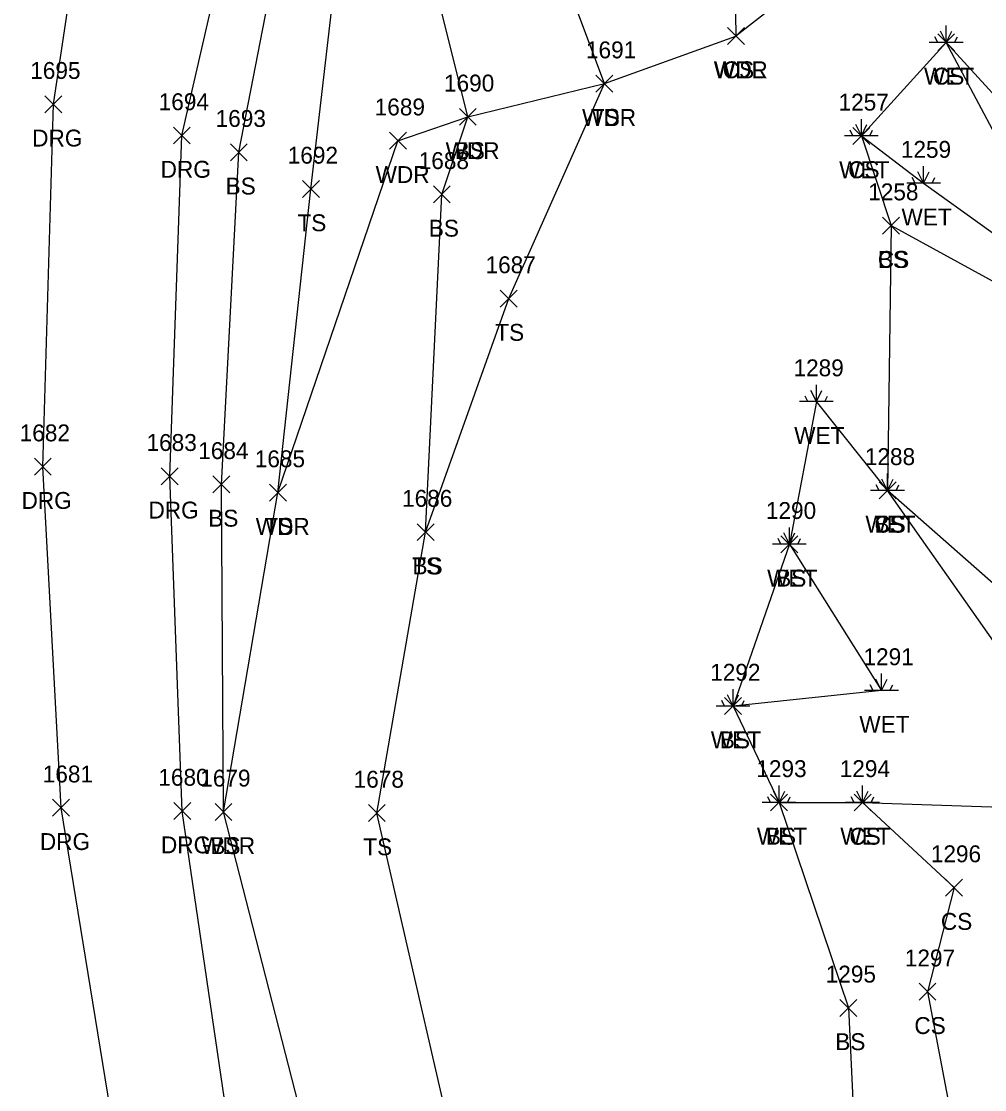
# Model space of a CAD drawing. Extents: x 1551995 to 1555700, y 777276 to 783130.
# Drawn here: x 1554729.1 to 1554843.1, y 777956 to 778082.5 of the extents above; entities that cross this region are included whole.
import ezdxf

# ---------------------------------------------------------------- set-up
doc = ezdxf.new("R2010")
doc.units = 0
for name, color, linetype in [('L_A', 7, 'Continuous'), ('L_I', 7, 'Continuous'), ('L_TIC', 7, 'Continuous'), ('LAWA', 7, 'Continuous'), ('LELB', 7, 'Continuous'), ('LWET', 7, 'Continuous'), ('R_A', 7, 'Continuous'), ('R_I', 7, 'Continuous'), ('R_TIC', 7, 'Continuous'), ('RDG', 7, 'Continuous')]:
    doc.layers.add(name, color=color, linetype=linetype)

msp = doc.modelspace()

# ---------------------------------------------------------------- linework, layer by layer
at = {"layer": 'L_TIC'}
for points in [[(1554812.64, 778079.72), (1554814.64, 778081.72)], [(1554814.64, 778079.72), (1554812.64, 778081.72)], [(1554812.64, 778079.72), (1554814.64, 778081.72)], [(1554814.64, 778079.72), (1554812.64, 778081.72)], [(1554812.64, 778079.72), (1554814.64, 778081.72)], [(1554814.64, 778079.72), (1554812.64, 778081.72)], [(1554837.51, 778078.97), (1554839.51, 778080.97)], [(1554839.51, 778078.97), (1554837.51, 778080.97)], [(1554797.07, 778074.08), (1554799.07, 778076.08)], [(1554799.07, 778074.08), (1554797.07, 778076.08)], [(1554797.07, 778074.08), (1554799.07, 778076.08)], [(1554799.07, 778074.08), (1554797.07, 778076.08)], [(1554780.91, 778070.15), (1554782.91, 778072.15)], [(1554782.91, 778070.15), (1554780.91, 778072.15)], [(1554780.91, 778070.15), (1554782.91, 778072.15)], [(1554782.91, 778070.15), (1554780.91, 778072.15)], [(1554772.64, 778067.32), (1554774.64, 778069.32)], [(1554774.64, 778067.32), (1554772.64, 778069.32)], [(1554827.48, 778067.89), (1554829.48, 778069.89)], [(1554829.48, 778067.89), (1554827.48, 778069.89)], [(1554753.81, 778065.96), (1554755.81, 778067.96)], [(1554755.81, 778065.96), (1554753.81, 778067.96)], [(1554762.34, 778061.61), (1554764.34, 778063.61)], [(1554764.34, 778061.61), (1554762.34, 778063.61)], [(1554777.84, 778060.97), (1554779.84, 778062.97)], [(1554779.84, 778060.97), (1554777.84, 778062.97)], [(1554830.99, 778057.27), (1554832.99, 778059.27)], [(1554832.99, 778057.27), (1554830.99, 778059.27)], [(1554830.99, 778057.27), (1554832.99, 778059.27)], [(1554832.99, 778057.27), (1554830.99, 778059.27)], [(1554785.75, 778048.64), (1554787.75, 778050.64)], [(1554787.75, 778048.64), (1554785.75, 778050.64)], [(1554751.75, 778026.64), (1554753.75, 778028.64)], [(1554753.75, 778026.64), (1554751.75, 778028.64)], [(1554758.44, 778025.67), (1554760.44, 778027.67)], [(1554760.44, 778025.67), (1554758.44, 778027.67)], [(1554758.44, 778025.67), (1554760.44, 778027.67)], [(1554760.44, 778025.67), (1554758.44, 778027.67)], [(1554830.58, 778025.93), (1554832.58, 778027.93)], [(1554832.58, 778025.93), (1554830.58, 778027.93)], [(1554830.58, 778025.93), (1554832.58, 778027.93)], [(1554832.58, 778025.93), (1554830.58, 778027.93)], [(1554775.92, 778020.99), (1554777.92, 778022.99)], [(1554777.92, 778020.99), (1554775.92, 778022.99)], [(1554775.92, 778020.99), (1554777.92, 778022.99)], [(1554777.92, 778020.99), (1554775.92, 778022.99)], [(1554818.96, 778019.55), (1554820.96, 778021.55)], [(1554820.96, 778019.55), (1554818.96, 778021.55)], [(1554812.29, 778000.4), (1554814.29, 778002.4)], [(1554814.29, 778000.4), (1554812.29, 778002.4)], [(1554817.74, 777988.99), (1554819.74, 777990.99)], [(1554819.74, 777988.99), (1554817.74, 777990.99)], [(1554827.62, 777988.99), (1554829.62, 777990.99)], [(1554829.62, 777988.99), (1554827.62, 777990.99)], [(1554752, 777987.87), (1554754, 777989.87)], [(1554754, 777987.87), (1554752, 777989.87)], [(1554752, 777987.87), (1554754, 777989.87)], [(1554754, 777987.87), (1554752, 777989.87)], [(1554770.14, 777987.74), (1554772.14, 777989.74)], [(1554772.14, 777987.74), (1554770.14, 777989.74)], [(1554838.45, 777978.91), (1554840.45, 777980.91)], [(1554840.45, 777978.91), (1554838.45, 777980.91)], [(1554835.31, 777966.58), (1554837.31, 777968.58)], [(1554837.31, 777966.58), (1554835.31, 777968.58)], [(1554825.95, 777964.67), (1554827.95, 777966.67)], [(1554827.95, 777964.67), (1554825.95, 777966.67)]]:
    msp.add_lwpolyline(points, dxfattribs=at)
at = {"layer": 'LAWA'}
for points in [[(1554935.43, 778396.62), (1554932.57, 778365.34), (1554927.8, 778334.86), (1554903.79, 778283.5), (1554902.47, 778219.43), (1554891.48, 778177.56), (1554886.36, 778149.25), (1554864.38, 778127.13), (1554855.54, 778103.27), (1554855.62, 778088.16), (1554832.42, 778095.39), (1554813.64, 778080.72)], [(1554753.38, 777699.82), (1554782.17, 777718.85), (1554781.09, 777755.32), (1554779.76, 777796.52), (1554779.3, 777834.65), (1554766.43, 777889.19), (1554764.95, 777942.26), (1554753, 777988.87), (1554759.44, 778026.67), (1554773.64, 778068.32), (1554781.91, 778071.15), (1554798.07, 778075.08), (1554813.64, 778080.72)]]:
    msp.add_lwpolyline(points, dxfattribs=at)
at = {"layer": 'LELB'}
for points in [[(1554968.28, 778312.04), (1554950, 778266.53), (1554926.49, 778220.19), (1554908.96, 778174.42), (1554896.48, 778148.26), (1554883.58, 778119.09), (1554877.33, 778100.58), (1554861.43, 778063.06), (1554849.04, 778068.43), (1554838.51, 778079.97)], [(1554808.26, 778210.35), (1554798.94, 778193.95), (1554801.39, 778167.85), (1554802.18, 778138.51), (1554810.18, 778108.91), (1554813.35, 778099.28), (1554813.64, 778080.72)], [(1554779.3, 777834.65), (1554783.83, 777890.02), (1554782.62, 777938.78), (1554771.14, 777988.74), (1554776.92, 778021.99), (1554786.75, 778049.64), (1554798.07, 778075.08), (1554788.09, 778101.73), (1554789.42, 778116.55), (1554786.7, 778124.19), (1554777.52, 778125.41), (1554776.84, 778134.51)], [(1554753, 777988.87), (1554752.75, 778027.64), (1554754.81, 778066.96), (1554760.51, 778096.21), (1554773.6, 778109.74), (1554789.42, 778116.55)], [(1554776.92, 778021.99), (1554778.84, 778061.97), (1554781.91, 778071.15), (1554776.47, 778093), (1554781.49, 778105.2), (1554773.6, 778109.74)], [(1554759.44, 778026.67), (1554763.34, 778062.61), (1554766.59, 778090.85), (1554770.54, 778094.09)], [(1554828.48, 778068.89), (1554831.99, 778058.27), (1554852.66, 778046.95), (1554846.7, 778013.58), (1554831.58, 778026.93)], [(1554831.99, 778058.27), (1554831.58, 778026.93)], [(1554819.96, 778020.55), (1554813.29, 778001.4)], [(1554818.74, 777989.99), (1554826.95, 777965.67), (1554828.21, 777938.79), (1554827.61, 777892.43), (1554825.56, 777859.47), (1554820.31, 777829.58), (1554817.04, 777800.55), (1554813.37, 777784.98), (1554810.59, 777751.68), (1554805.09, 777735), (1554803.57, 777724.87), (1554801.62, 777701.82), (1554799.08, 777679.52), (1554798, 777658.89), (1554794.95, 777639.81), (1554778.13, 777607.5), (1554759.36, 777559.57), (1554752.31, 777545.79)], [(1554828.62, 777989.99), (1554839.45, 777979.91), (1554836.31, 777967.58), (1554843.93, 777927.48), (1554845.21, 777880.49), (1554844.2, 777852.94), (1554834.62, 777824.64), (1554828.42, 777780.47), (1554821.65, 777751.51), (1554810.59, 777751.68)]]:
    msp.add_lwpolyline(points, dxfattribs=at)
at = {"layer": 'LWET'}
for p, q in [((1554838.51, 778079.97), (1554838.51, 778081.97)), ((1554837.51, 778079.97), (1554837.18, 778080.64)), ((1554838.51, 778079.97), (1554837.85, 778081.3)), ((1554838.51, 778079.97), (1554839.18, 778081.3)), ((1554839.51, 778079.97), (1554839.85, 778080.64)), ((1554840.51, 778079.97), (1554836.51, 778079.97)), ((1554828.48, 778068.89), (1554827.81, 778070.23)), ((1554828.48, 778068.89), (1554828.48, 778070.89)), ((1554828.48, 778068.89), (1554829.14, 778070.23)), ((1554830.48, 778068.89), (1554826.48, 778068.89)), ((1554827.48, 778068.89), (1554827.14, 778069.56)), ((1554829.48, 778068.89), (1554829.81, 778069.56)), ((1554835.85, 778063.3), (1554835.85, 778065.3)), ((1554834.85, 778063.3), (1554834.51, 778063.97)), ((1554835.85, 778063.3), (1554835.18, 778064.64)), ((1554835.85, 778063.3), (1554836.51, 778064.64)), ((1554836.85, 778063.3), (1554837.18, 778063.97)), ((1554837.85, 778063.3), (1554833.85, 778063.3)), ((1554823.16, 778037.44), (1554822.49, 778038.77)), ((1554823.16, 778037.44), (1554823.16, 778039.44)), ((1554823.16, 778037.44), (1554823.82, 778038.77)), ((1554825.16, 778037.44), (1554821.16, 778037.44)), ((1554822.16, 778037.44), (1554821.82, 778038.1)), ((1554824.16, 778037.44), (1554824.49, 778038.1)), ((1554831.58, 778026.93), (1554830.91, 778028.26)), ((1554831.58, 778026.93), (1554831.58, 778028.93)), ((1554831.58, 778026.93), (1554832.25, 778028.26)), ((1554830.58, 778026.93), (1554830.25, 778027.6)), ((1554832.58, 778026.93), (1554832.91, 778027.6)), ((1554833.58, 778026.93), (1554829.58, 778026.93)), ((1554819.96, 778020.55), (1554819.96, 778022.55)), ((1554818.96, 778020.55), (1554818.62, 778021.22)), ((1554819.96, 778020.55), (1554819.29, 778021.89)), ((1554819.96, 778020.55), (1554820.62, 778021.89)), ((1554820.96, 778020.55), (1554821.29, 778021.22)), ((1554821.96, 778020.55), (1554817.96, 778020.55)), ((1554830.86, 778003.24), (1554830.19, 778004.57)), ((1554830.86, 778003.24), (1554830.86, 778005.24)), ((1554830.86, 778003.24), (1554831.53, 778004.57)), ((1554813.29, 778001.4), (1554813.29, 778003.4)), ((1554832.86, 778003.24), (1554828.86, 778003.24)), ((1554829.86, 778003.24), (1554829.53, 778003.9)), ((1554831.86, 778003.24), (1554832.19, 778003.9)), ((1554812.29, 778001.4), (1554811.95, 778002.07)), ((1554813.29, 778001.4), (1554812.62, 778002.73)), ((1554813.29, 778001.4), (1554813.95, 778002.73)), ((1554814.29, 778001.4), (1554814.62, 778002.07)), ((1554815.29, 778001.4), (1554811.29, 778001.4)), ((1554818.74, 777989.99), (1554818.74, 777991.99)), ((1554828.62, 777989.99), (1554828.62, 777991.99)), ((1554817.74, 777989.99), (1554817.41, 777990.66)), ((1554818.74, 777989.99), (1554818.07, 777991.33)), ((1554818.74, 777989.99), (1554819.41, 777991.33)), ((1554819.74, 777989.99), (1554820.07, 777990.66)), ((1554827.62, 777989.99), (1554827.28, 777990.66)), ((1554828.62, 777989.99), (1554827.95, 777991.33)), ((1554828.62, 777989.99), (1554829.28, 777991.33)), ((1554829.62, 777989.99), (1554829.95, 777990.66)), ((1554820.74, 777989.99), (1554816.74, 777989.99)), ((1554830.62, 777989.99), (1554826.62, 777989.99))]:
    msp.add_line(p, q, dxfattribs=at)
for points in [[(1554899.62, 778064.01), (1554891.87, 778065.74), (1554875.6, 778057.42), (1554858.79, 778055.84), (1554846.25, 778065.45), (1554838.51, 778079.97), (1554828.48, 778068.89), (1554835.85, 778063.3), (1554853.84, 778050.34), (1554871.64, 778048.29), (1554884.34, 778050.68), (1554889.87, 778042.09)], [(1554882.71, 778000.01), (1554868.64, 778003.69), (1554846.36, 778005.87), (1554831.58, 778026.93), (1554823.16, 778037.44), (1554819.96, 778020.55), (1554830.86, 778003.24), (1554813.29, 778001.4), (1554818.74, 777989.99), (1554828.62, 777989.99), (1554846.21, 777989.4), (1554860.04, 777985), (1554871.69, 777971.47)]]:
    msp.add_lwpolyline(points, dxfattribs=at)
at = {"layer": 'R_TIC'}
for points in [[(1554731.87, 778071.64), (1554733.87, 778073.64)], [(1554733.87, 778071.64), (1554731.87, 778073.64)], [(1554747.07, 778067.94), (1554749.07, 778069.94)], [(1554749.07, 778067.94), (1554747.07, 778069.94)], [(1554730.62, 778028.74), (1554732.62, 778030.74)], [(1554732.62, 778028.74), (1554730.62, 778030.74)], [(1554745.63, 778027.6), (1554747.63, 778029.6)], [(1554747.63, 778027.6), (1554745.63, 778029.6)], [(1554732.78, 777988.36), (1554734.78, 777990.36)], [(1554734.78, 777988.36), (1554732.78, 777990.36)], [(1554747.12, 777987.97), (1554749.12, 777989.97)], [(1554749.12, 777987.97), (1554747.12, 777989.97)]]:
    msp.add_lwpolyline(points, dxfattribs=at)
at = {"layer": 'RDG'}
for points in [[(1554731.76, 777736.57), (1554744.54, 777760.39), (1554749.58, 777791.25), (1554744.63, 777884.27), (1554742.18, 777937.77), (1554733.78, 777989.36), (1554731.62, 778029.74), (1554732.87, 778072.64), (1554738.87, 778112.72), (1554741.1, 778122.89), (1554752.14, 778165.58), (1554757.04, 778182.47), (1554765.14, 778213.69), (1554774.89, 778246.18), (1554785.77, 778269.3), (1554800.7, 778290.2), (1554833.81, 778326.22), (1554863.94, 778353.44), (1554894.55, 778381.82), (1554916.32, 778408.8)], [(1554765.41, 777786.83), (1554760.87, 777887.93), (1554755.21, 777940.6), (1554748.12, 777988.97), (1554746.63, 778028.6), (1554748.07, 778068.94), (1554755.05, 778099.35), (1554759.31, 778115.55), (1554764.29, 778135.87), (1554767.84, 778151.77), (1554770.94, 778162.89), (1554771.35, 778163.02), (1554773.41, 778171.97), (1554775.55, 778183.39), (1554780.94, 778209.88), (1554780.41, 778210.35), (1554788.23, 778232), (1554795.94, 778253.78), (1554801.81, 778267.78), (1554821.53, 778293.59), (1554841.19, 778314.82), (1554873.15, 778342.35), (1554907.49, 778367.57), (1554931.47, 778399.39)]]:
    msp.add_lwpolyline(points, dxfattribs=at)

# ---------------------------------------------------------------- texts
at = {"layer": 'L_A'}
for s, p in [('WDR', (1554811.01, 778075.72)), ('WDL', (1554811.06, 778075.72)), ('CS', (1554812.08, 778075.72)), ('WET', (1554835.89, 778074.97)), ('CS', (1554836.95, 778074.97)), ('WDR', (1554795.43, 778070.08)), ('TS', (1554796.47, 778070.08)), ('WDR', (1554779.28, 778066.15)), ('BS', (1554780.36, 778066.15)), ('WDR', (1554771, 778063.32)), ('WET', (1554825.85, 778063.89)), ('CS', (1554826.92, 778063.89)), ('BS', (1554753.25, 778061.96)), ('WET', (1554833.23, 778058.3)), ('TS', (1554761.75, 778057.61)), ('BS', (1554777.29, 778056.97)), ('CS', (1554830.43, 778053.27)), ('BS', (1554830.43, 778053.27)), ('TS', (1554785.16, 778044.64)), ('WET', (1554820.53, 778032.44)), ('BS', (1554751.19, 778022.64)), ('WDR', (1554756.81, 778021.67)), ('TS', (1554757.85, 778021.67)), ('WET', (1554828.96, 778021.93)), ('CS', (1554830.02, 778021.93)), ('BS', (1554830.02, 778021.93)), ('TS', (1554775.33, 778016.99)), ('BS', (1554775.36, 778016.99)), ('WET', (1554817.33, 778015.55)), ('BS', (1554818.4, 778015.55)), ('WET', (1554828.24, 777998.24)), ('WET', (1554810.67, 777996.4)), ('BS', (1554811.73, 777996.4)), ('WET', (1554816.12, 777984.99)), ('BS', (1554817.18, 777984.99)), ('WET', (1554825.99, 777984.99)), ('CS', (1554827.06, 777984.99)), ('WDR', (1554750.36, 777983.87)), ('BS', (1554751.44, 777983.87)), ('TS', (1554769.54, 777983.74)), ('CS', (1554837.89, 777974.91)), ('CS', (1554834.75, 777962.58)), ('BS', (1554825.39, 777960.67))]:
    msp.add_text(s, height=2, dxfattribs=at).set_placement(p)
at = {"layer": 'L_I'}
for s, p in [('1691', (1554795.89, 778078.08)), ('1691', (1554795.89, 778078.08)), ('1690', (1554779.09, 778074.15)), ('1690', (1554779.09, 778074.15)), ('1257', (1554825.78, 778071.89)), ('1257', (1554825.78, 778071.89)), ('1689', (1554770.89, 778071.32)), ('1693', (1554752.07, 778069.96)), ('1692', (1554760.6, 778065.61)), ('1259', (1554833.15, 778066.3)), ('1688', (1554776.1, 778064.97)), ('1258', (1554829.29, 778061.27)), ('1258', (1554829.29, 778061.27)), ('1687', (1554784.01, 778052.64)), ('1289', (1554820.45, 778040.44)), ('1684', (1554750.01, 778030.64)), ('1685', (1554756.7, 778029.67)), ('1685', (1554756.7, 778029.67)), ('1288', (1554828.89, 778029.93)), ('1288', (1554828.89, 778029.93)), ('1288', (1554828.89, 778029.93)), ('1686', (1554774.13, 778024.99)), ('1686', (1554774.13, 778024.99)), ('1290', (1554817.18, 778023.55)), ('1290', (1554817.18, 778023.55)), ('1291', (1554828.73, 778006.24)), ('1292', (1554810.59, 778004.4)), ('1292', (1554810.59, 778004.4)), ('1293', (1554816.05, 777992.99)), ('1293', (1554816.05, 777992.99)), ('1294', (1554825.92, 777992.99)), ('1294', (1554825.92, 777992.99)), ('1679', (1554750.25, 777991.87)), ('1679', (1554750.25, 777991.87)), ('1678', (1554768.4, 777991.74)), ('1296', (1554836.7, 777982.91)), ('1297', (1554833.62, 777970.58)), ('1295', (1554824.26, 777968.67))]:
    msp.add_text(s, height=2, dxfattribs=at).set_placement(p)
at = {"layer": 'R_A'}
for p in [(1554730.36, 778067.64), (1554745.56, 778063.94), (1554729.1, 778024.74), (1554744.12, 778023.6), (1554731.27, 777984.36), (1554745.6, 777983.97)]:
    msp.add_text('DRG', height=2, dxfattribs=at).set_placement(p)
at = {"layer": 'R_I'}
for s, p in [('1695', (1554730.13, 778075.64)), ('1694', (1554745.33, 778071.94)), ('1682', (1554728.88, 778032.74)), ('1683', (1554743.89, 778031.6)), ('1681', (1554731.61, 777992.36)), ('1680', (1554745.29, 777991.97))]:
    msp.add_text(s, height=2, dxfattribs=at).set_placement(p)

doc.saveas('drawing.dxf')
